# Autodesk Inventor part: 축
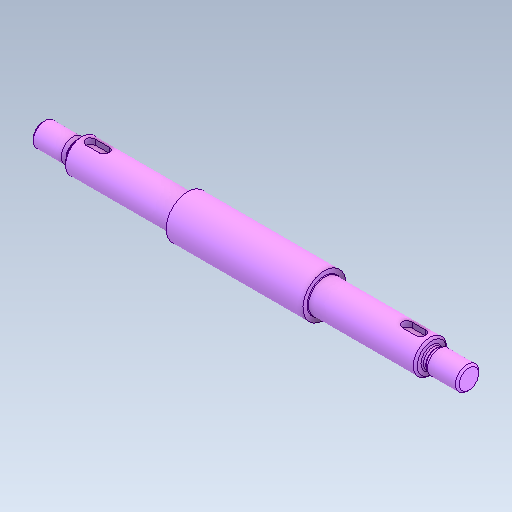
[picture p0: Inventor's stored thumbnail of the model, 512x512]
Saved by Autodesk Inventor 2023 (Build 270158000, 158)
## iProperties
Created: 2025-03
Part Number: 축
Material: 강철, 탄소
Document SubType Name: Modeling
Designer: Admin
Density: 7.85 g/cm^3
Appearance: 기본값
Author: jhkim
Sending System: Autodesk Inventor 2025
Preprocessor: ST-DEVELOPER v20
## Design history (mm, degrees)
feature "솔리드1"
node "솔리드2"
